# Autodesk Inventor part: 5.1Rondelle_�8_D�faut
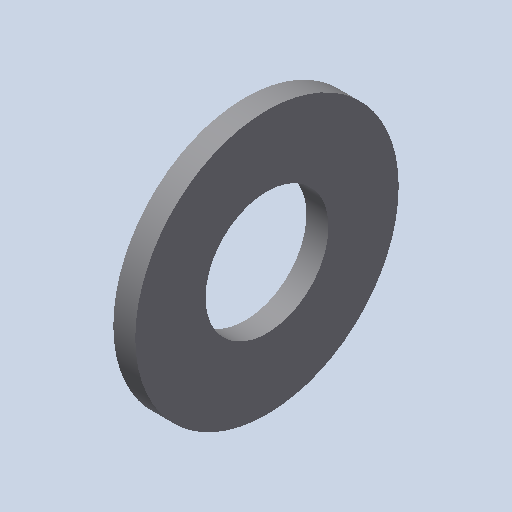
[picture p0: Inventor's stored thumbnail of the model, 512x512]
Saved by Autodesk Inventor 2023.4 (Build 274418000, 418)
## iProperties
Created: 2011-01
Part Number: 5.1Rondelle_�8_D�faut
Document SubType Name: Modeling
Designer: eric
Density: 1 g/cm^3
Mass: 0.298577 g
Surface Area: 5.2251 cm^2
Volume: 0.298577 cm^3
Material: Générique
Appearance: Par défaut
Author: eric
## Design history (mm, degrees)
feature "Base1"
node "Corps solides"
node "Corps surfaciques"
node "Solide1"
